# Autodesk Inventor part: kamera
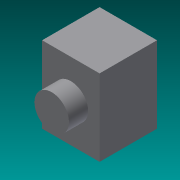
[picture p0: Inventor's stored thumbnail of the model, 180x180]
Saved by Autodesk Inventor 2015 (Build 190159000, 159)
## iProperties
Created: 2016-02
Part Number: kamera
Material: Generic
Document SubType Name: Modeling
Designer: Rafał
Density: 1 g/cm^3
Appearance: Default
Author: Rafał
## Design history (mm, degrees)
sketch "Sketch1"
  geometry: C1 r 9 at (0, 0); 1 further point
  constraints: 1 centre point, 1 coincident
  dimensions: "d0" = 18 diameter of C1
extrude "Extrusion1" new body sketch "Sketch1" distance "d1" = 10; taper "d2" = 0 deg
sketch "Sketch2"
  geometry: L1 (15, -20)-(-15, -20); L2 (-15, -20)-(-15, 20); L3 (-15, 20)-(15, 20); L4 (15, 20)-(15, -20); L5 (15, -20)-(-15, 20); L6 (-15, -20)-(15, 20); 1 further point
  constraints: 12 end point, 2 midpoint, 2 parallel, 1 horizontal, 1 perpendicular
  dimensions: "d3" = 30 distance of L2.end L3.end; "d4" = 40 distance of L1.end L2.end
extrude "Extrusion2" join sketch "Sketch2" distance "d5" = 30; taper "d6" = 0 deg
body "Solid1"
